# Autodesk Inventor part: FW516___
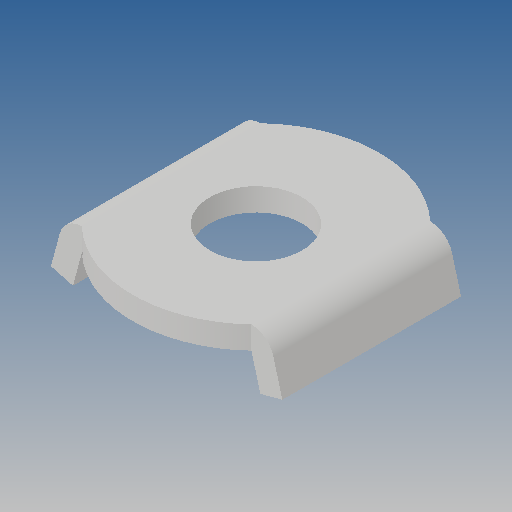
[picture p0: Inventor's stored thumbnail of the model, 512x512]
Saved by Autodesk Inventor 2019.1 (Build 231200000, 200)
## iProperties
Created: 2012-09
Part Number: FW516___
Material: Ogólny
Document SubType Name: Modeling
Designer: CADENGINEERING4
Density: 1 g/cm^3
Appearance: Domyślna
Author: CADENGINEERING4
Revision Number: ÈÎºÎ
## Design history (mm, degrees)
feature "NONE"
node "Bryła1"
